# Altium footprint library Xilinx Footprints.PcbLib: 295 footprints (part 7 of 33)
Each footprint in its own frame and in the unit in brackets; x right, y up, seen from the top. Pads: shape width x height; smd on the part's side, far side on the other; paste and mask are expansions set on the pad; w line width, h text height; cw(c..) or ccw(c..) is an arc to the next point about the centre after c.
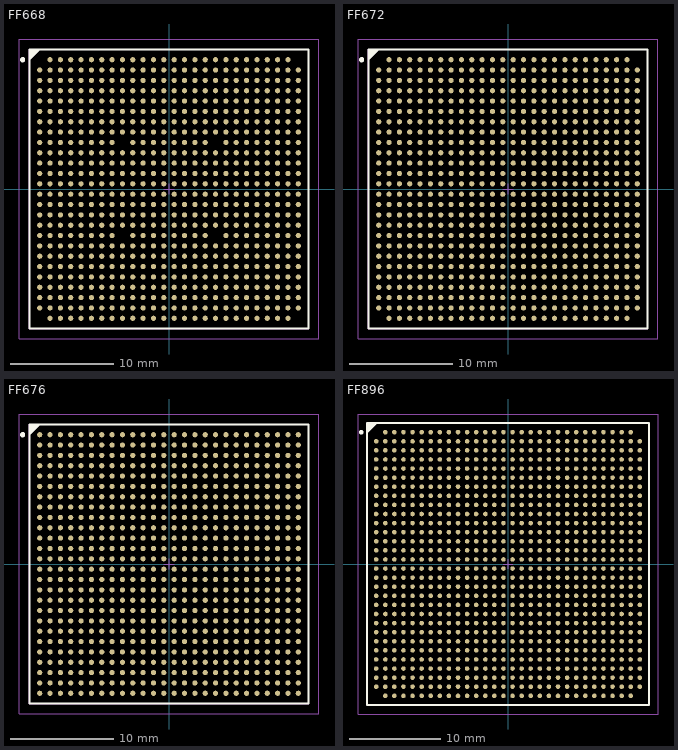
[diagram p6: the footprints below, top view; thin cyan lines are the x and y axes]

## FF668 [mm] "668-Ball Flip Chip Fine Pitch Ball Grid Array (FF668)"
height 2.85
pads (668):
  round 0.5 smd: A2(-11.5,12.5) A3(-10.5,12.5) A4(-9.5,12.5) A5(-8.5,12.5) A6(-7.5,12.5) A7(-6.5,12.5) A8(-5.5,12.5) A9(-4.5,12.5) A10(-3.5,12.5) A11(-2.5,12.5) A12(-1.5,12.5) A13(-0.5,12.5) A14(0.5,12.5) A15(1.5,12.5) A16(2.5,12.5) A17(3.5,12.5) A18(4.5,12.5) A19(5.5,12.5) A20(6.5,12.5) A21(7.5,12.5) A22(8.5,12.5) A23(9.5,12.5) A24(10.5,12.5) A25(11.5,12.5) AA1(-12.5,-7.5) AA2(-11.5,-7.5) AA3(-10.5,-7.5) AA4(-9.5,-7.5) AA5(-8.5,-7.5) AA6(-7.5,-7.5) AA7(-6.5,-7.5) AA8(-5.5,-7.5) AA9(-4.5,-7.5) AA10(-3.5,-7.5) AA11(-2.5,-7.5) AA12(-1.5,-7.5) AA13(-0.5,-7.5) AA14(0.5,-7.5) AA15(1.5,-7.5) AA16(2.5,-7.5) AA17(3.5,-7.5) AA18(4.5,-7.5) AA19(5.5,-7.5) AA20(6.5,-7.5) AA21(7.5,-7.5) AA22(8.5,-7.5) AA23(9.5,-7.5) AA24(10.5,-7.5) AA25(11.5,-7.5) AA26(12.5,-7.5) AB1(-12.5,-8.5) AB2(-11.5,-8.5) AB3(-10.5,-8.5) AB4(-9.5,-8.5) AB5(-8.5,-8.5) AB6(-7.5,-8.5) AB7(-6.5,-8.5) AB8(-5.5,-8.5) AB9(-4.5,-8.5) AB10(-3.5,-8.5) AB11(-2.5,-8.5) AB12(-1.5,-8.5) AB13(-0.5,-8.5) AB14(0.5,-8.5) AB15(1.5,-8.5) AB16(2.5,-8.5) AB17(3.5,-8.5) AB18(4.5,-8.5) AB19(5.5,-8.5) AB20(6.5,-8.5) AB21(7.5,-8.5) AB22(8.5,-8.5) AB23(9.5,-8.5) AB24(10.5,-8.5) AB25(11.5,-8.5) AB26(12.5,-8.5) AC1(-12.5,-9.5) AC2(-11.5,-9.5) AC3(-10.5,-9.5) AC4(-9.5,-9.5) AC5(-8.5,-9.5) AC6(-7.5,-9.5) AC7(-6.5,-9.5) AC8(-5.5,-9.5) AC9(-4.5,-9.5) AC10(-3.5,-9.5) AC11(-2.5,-9.5) AC12(-1.5,-9.5) AC13(-0.5,-9.5) AC14(0.5,-9.5) AC15(1.5,-9.5) AC16(2.5,-9.5) AC17(3.5,-9.5) AC18(4.5,-9.5) AC19(5.5,-9.5) AC20(6.5,-9.5) AC21(7.5,-9.5) AC22(8.5,-9.5) AC23(9.5,-9.5) AC24(10.5,-9.5) AC25(11.5,-9.5) AC26(12.5,-9.5) AD1(-12.5,-10.5) AD2(-11.5,-10.5) AD3(-10.5,-10.5) AD4(-9.5,-10.5) AD5(-8.5,-10.5) AD6(-7.5,-10.5) AD7(-6.5,-10.5) AD8(-5.5,-10.5) AD9(-4.5,-10.5) AD10(-3.5,-10.5) AD11(-2.5,-10.5) AD12(-1.5,-10.5) AD13(-0.5,-10.5) AD14(0.5,-10.5) AD15(1.5,-10.5) AD16(2.5,-10.5) AD17(3.5,-10.5) AD18(4.5,-10.5) AD19(5.5,-10.5) AD20(6.5,-10.5) AD21(7.5,-10.5) AD22(8.5,-10.5) AD23(9.5,-10.5) AD24(10.5,-10.5) AD25(11.5,-10.5) AD26(12.5,-10.5) AE1(-12.5,-11.5) AE2(-11.5,-11.5) AE3(-10.5,-11.5) AE4(-9.5,-11.5) AE5(-8.5,-11.5) AE6(-7.5,-11.5) AE7(-6.5,-11.5) AE8(-5.5,-11.5) AE9(-4.5,-11.5) AE10(-3.5,-11.5) AE11(-2.5,-11.5) AE12(-1.5,-11.5) AE13(-0.5,-11.5) AE14(0.5,-11.5) AE15(1.5,-11.5) AE16(2.5,-11.5) AE17(3.5,-11.5) AE18(4.5,-11.5) AE19(5.5,-11.5) AE20(6.5,-11.5) AE21(7.5,-11.5) AE22(8.5,-11.5) AE23(9.5,-11.5) AE24(10.5,-11.5) AE25(11.5,-11.5) AE26(12.5,-11.5) AF2(-11.5,-12.5) AF3(-10.5,-12.5) AF4(-9.5,-12.5) AF5(-8.5,-12.5) AF6(-7.5,-12.5) AF7(-6.5,-12.5) AF8(-5.5,-12.5) AF9(-4.5,-12.5) AF10(-3.5,-12.5) AF11(-2.5,-12.5) AF12(-1.5,-12.5) AF13(-0.5,-12.5) AF14(0.5,-12.5) AF15(1.5,-12.5) AF16(2.5,-12.5) AF17(3.5,-12.5) AF18(4.5,-12.5) AF19(5.5,-12.5) AF20(6.5,-12.5) AF21(7.5,-12.5) AF22(8.5,-12.5) AF23(9.5,-12.5) AF24(10.5,-12.5) AF25(11.5,-12.5) B1(-12.5,11.5) B2(-11.5,11.5) B3(-10.5,11.5) B4(-9.5,11.5) B5(-8.5,11.5) B6(-7.5,11.5) B7(-6.5,11.5) B8(-5.5,11.5) B9(-4.5,11.5) B10(-3.5,11.5) B11(-2.5,11.5) B12(-1.5,11.5) B13(-0.5,11.5) B14(0.5,11.5) B15(1.5,11.5) B16(2.5,11.5) B17(3.5,11.5) B18(4.5,11.5) B19(5.5,11.5) B20(6.5,11.5) B21(7.5,11.5) B22(8.5,11.5) B23(9.5,11.5) B24(10.5,11.5) B25(11.5,11.5) B26(12.5,11.5) C1(-12.5,10.5) C2(-11.5,10.5) C3(-10.5,10.5) C4(-9.5,10.5) C5(-8.5,10.5) C6(-7.5,10.5) C7(-6.5,10.5) C8(-5.5,10.5) C9(-4.5,10.5) C10(-3.5,10.5) C11(-2.5,10.5) C12(-1.5,10.5) C13(-0.5,10.5) C14(0.5,10.5) C15(1.5,10.5) C16(2.5,10.5) C17(3.5,10.5) C18(4.5,10.5) C19(5.5,10.5) C20(6.5,10.5) C21(7.5,10.5) C22(8.5,10.5) C23(9.5,10.5) C24(10.5,10.5) C25(11.5,10.5) C26(12.5,10.5) D1(-12.5,9.5) D2(-11.5,9.5) D3(-10.5,9.5) D4(-9.5,9.5) D5(-8.5,9.5) D6(-7.5,9.5) D7(-6.5,9.5) D8(-5.5,9.5) D9(-4.5,9.5) D10(-3.5,9.5) D11(-2.5,9.5) D12(-1.5,9.5) D13(-0.5,9.5) D14(0.5,9.5) D15(1.5,9.5) D16(2.5,9.5) D17(3.5,9.5) D18(4.5,9.5) D19(5.5,9.5) D20(6.5,9.5) D21(7.5,9.5) D22(8.5,9.5) D23(9.5,9.5) D24(10.5,9.5) D25(11.5,9.5) D26(12.5,9.5) E1(-12.5,8.5) E2(-11.5,8.5) E3(-10.5,8.5) E4(-9.5,8.5) E5(-8.5,8.5) E6(-7.5,8.5) E7(-6.5,8.5) E8(-5.5,8.5) E9(-4.5,8.5) E10(-3.5,8.5) E11(-2.5,8.5) E12(-1.5,8.5) E13(-0.5,8.5) E14(0.5,8.5) E15(1.5,8.5) E16(2.5,8.5) E17(3.5,8.5) E18(4.5,8.5) E19(5.5,8.5) E20(6.5,8.5) E21(7.5,8.5) E22(8.5,8.5) E23(9.5,8.5) E24(10.5,8.5) E25(11.5,8.5) E26(12.5,8.5) F1(-12.5,7.5) F2(-11.5,7.5) F3(-10.5,7.5) F4(-9.5,7.5) F5(-8.5,7.5) F6(-7.5,7.5) F7(-6.5,7.5) F8(-5.5,7.5) F9(-4.5,7.5) F10(-3.5,7.5) F11(-2.5,7.5) F12(-1.5,7.5) F13(-0.5,7.5) F14(0.5,7.5) F15(1.5,7.5) F16(2.5,7.5) F17(3.5,7.5) F18(4.5,7.5) F19(5.5,7.5) F20(6.5,7.5) F21(7.5,7.5) F22(8.5,7.5) F23(9.5,7.5) F24(10.5,7.5) F25(11.5,7.5) F26(12.5,7.5) G1(-12.5,6.5) G2(-11.5,6.5) G3(-10.5,6.5) G4(-9.5,6.5) G5(-8.5,6.5) G6(-7.5,6.5) G7(-6.5,6.5) G8(-5.5,6.5) G9(-4.5,6.5) G10(-3.5,6.5) G11(-2.5,6.5) G12(-1.5,6.5) G13(-0.5,6.5) G14(0.5,6.5) G15(1.5,6.5) G16(2.5,6.5) G17(3.5,6.5) G18(4.5,6.5) G19(5.5,6.5) G20(6.5,6.5) G21(7.5,6.5) G22(8.5,6.5) G23(9.5,6.5) G24(10.5,6.5) G25(11.5,6.5) G26(12.5,6.5) H1(-12.5,5.5) H2(-11.5,5.5) H3(-10.5,5.5) H4(-9.5,5.5) H5(-8.5,5.5) H6(-7.5,5.5) H7(-6.5,5.5) H8(-5.5,5.5) H9(-4.5,5.5) H10(-3.5,5.5) H11(-2.5,5.5) H12(-1.5,5.5) H13(-0.5,5.5) H14(0.5,5.5) H15(1.5,5.5) H16(2.5,5.5) H17(3.5,5.5) H18(4.5,5.5) H19(5.5,5.5) H20(6.5,5.5) H21(7.5,5.5) H22(8.5,5.5) H23(9.5,5.5) H24(10.5,5.5) H25(11.5,5.5) H26(12.5,5.5) J1(-12.5,4.5) J2(-11.5,4.5) J3(-10.5,4.5) J4(-9.5,4.5) J5(-8.5,4.5) J6(-7.5,4.5) J7(-6.5,4.5) J8(-5.5,4.5) J10(-3.5,4.5) J11(-2.5,4.5) J12(-1.5,4.5) J13(-0.5,4.5) J14(0.5,4.5) J15(1.5,4.5) J16(2.5,4.5) J17(3.5,4.5) J19(5.5,4.5) J20(6.5,4.5) J21(7.5,4.5) J22(8.5,4.5) J23(9.5,4.5) J24(10.5,4.5) J25(11.5,4.5) J26(12.5,4.5) K1(-12.5,3.5) K2(-11.5,3.5) K3(-10.5,3.5) K4(-9.5,3.5) K5(-8.5,3.5) K6(-7.5,3.5) K7(-6.5,3.5) K8(-5.5,3.5) K9(-4.5,3.5) K10(-3.5,3.5) K11(-2.5,3.5) K12(-1.5,3.5) K13(-0.5,3.5) K14(0.5,3.5) K15(1.5,3.5) K16(2.5,3.5) K17(3.5,3.5) K18(4.5,3.5) K19(5.5,3.5) K20(6.5,3.5) K21(7.5,3.5) K22(8.5,3.5) K23(9.5,3.5) K24(10.5,3.5) K25(11.5,3.5) K26(12.5,3.5) L1(-12.5,2.5) L2(-11.5,2.5) L3(-10.5,2.5) L4(-9.5,2.5) L5(-8.5,2.5) L6(-7.5,2.5) L7(-6.5,2.5) L8(-5.5,2.5) L9(-4.5,2.5) L10(-3.5,2.5) L11(-2.5,2.5) L12(-1.5,2.5) L13(-0.5,2.5) L14(0.5,2.5) L15(1.5,2.5) L16(2.5,2.5) L17(3.5,2.5) L18(4.5,2.5) L19(5.5,2.5) L20(6.5,2.5) L21(7.5,2.5) L22(8.5,2.5) L23(9.5,2.5) L24(10.5,2.5) L25(11.5,2.5) L26(12.5,2.5) M1(-12.5,1.5) M2(-11.5,1.5) M3(-10.5,1.5) M4(-9.5,1.5) M5(-8.5,1.5) M6(-7.5,1.5) M7(-6.5,1.5) M8(-5.5,1.5) M9(-4.5,1.5) M10(-3.5,1.5) M11(-2.5,1.5) M12(-1.5,1.5) M13(-0.5,1.5) M14(0.5,1.5) M15(1.5,1.5) M16(2.5,1.5) M17(3.5,1.5) M18(4.5,1.5) M19(5.5,1.5) M20(6.5,1.5) M21(7.5,1.5) M22(8.5,1.5) M23(9.5,1.5) M24(10.5,1.5) M25(11.5,1.5) M26(12.5,1.5) N1(-12.5,0.5) N2(-11.5,0.5) N3(-10.5,0.5) N4(-9.5,0.5) N5(-8.5,0.5) N6(-7.5,0.5) N7(-6.5,0.5) N8(-5.5,0.5) N9(-4.5,0.5) N10(-3.5,0.5) N11(-2.5,0.5) N12(-1.5,0.5) N13(-0.5,0.5) N14(0.5,0.5) N15(1.5,0.5) N16(2.5,0.5) N17(3.5,0.5) N18(4.5,0.5) N19(5.5,0.5) N20(6.5,0.5) N21(7.5,0.5) N22(8.5,0.5) N23(9.5,0.5) N24(10.5,0.5) N25(11.5,0.5) N26(12.5,0.5) P1(-12.5,-0.5) P2(-11.5,-0.5) P3(-10.5,-0.5) P4(-9.5,-0.5) P5(-8.5,-0.5) P6(-7.5,-0.5) P7(-6.5,-0.5) P8(-5.5,-0.5) P9(-4.5,-0.5) P10(-3.5,-0.5) P11(-2.5,-0.5) P12(-1.5,-0.5) P13(-0.5,-0.5) P14(0.5,-0.5) P15(1.5,-0.5) P16(2.5,-0.5) P17(3.5,-0.5) P18(4.5,-0.5) P19(5.5,-0.5) P20(6.5,-0.5) P21(7.5,-0.5) P22(8.5,-0.5) P23(9.5,-0.5) P24(10.5,-0.5) P25(11.5,-0.5) P26(12.5,-0.5) R1(-12.5,-1.5) R2(-11.5,-1.5) R3(-10.5,-1.5) R4(-9.5,-1.5) R5(-8.5,-1.5) R6(-7.5,-1.5) R7(-6.5,-1.5) R8(-5.5,-1.5) R9(-4.5,-1.5) R10(-3.5,-1.5) R11(-2.5,-1.5) R12(-1.5,-1.5) R13(-0.5,-1.5) R14(0.5,-1.5) R15(1.5,-1.5) R16(2.5,-1.5) R17(3.5,-1.5) R18(4.5,-1.5) R19(5.5,-1.5) R20(6.5,-1.5) R21(7.5,-1.5) R22(8.5,-1.5) R23(9.5,-1.5) R24(10.5,-1.5) R25(11.5,-1.5) R26(12.5,-1.5) T1(-12.5,-2.5) T2(-11.5,-2.5) T3(-10.5,-2.5) T4(-9.5,-2.5) T5(-8.5,-2.5) T6(-7.5,-2.5) T7(-6.5,-2.5) T8(-5.5,-2.5) T9(-4.5,-2.5) T10(-3.5,-2.5) T11(-2.5,-2.5) T12(-1.5,-2.5) T13(-0.5,-2.5) T14(0.5,-2.5) T15(1.5,-2.5) T16(2.5,-2.5) T17(3.5,-2.5) T18(4.5,-2.5) T19(5.5,-2.5) T20(6.5,-2.5) T21(7.5,-2.5) T22(8.5,-2.5) T23(9.5,-2.5) T24(10.5,-2.5) T25(11.5,-2.5) T26(12.5,-2.5) U1(-12.5,-3.5) U2(-11.5,-3.5) U3(-10.5,-3.5) U4(-9.5,-3.5) U5(-8.5,-3.5) U6(-7.5,-3.5) U7(-6.5,-3.5) U8(-5.5,-3.5) U9(-4.5,-3.5) U10(-3.5,-3.5) U11(-2.5,-3.5) U12(-1.5,-3.5) U13(-0.5,-3.5) U14(0.5,-3.5) U15(1.5,-3.5) U16(2.5,-3.5) U17(3.5,-3.5) U18(4.5,-3.5) U19(5.5,-3.5) U20(6.5,-3.5) U21(7.5,-3.5) U22(8.5,-3.5) U23(9.5,-3.5) U24(10.5,-3.5) U25(11.5,-3.5) U26(12.5,-3.5) V1(-12.5,-4.5) V2(-11.5,-4.5) V3(-10.5,-4.5) V4(-9.5,-4.5) V5(-8.5,-4.5) V6(-7.5,-4.5) V7(-6.5,-4.5) V8(-5.5,-4.5) V10(-3.5,-4.5) V11(-2.5,-4.5) V12(-1.5,-4.5) V13(-0.5,-4.5) V14(0.5,-4.5) V15(1.5,-4.5) V16(2.5,-4.5) V17(3.5,-4.5) V19(5.5,-4.5) V20(6.5,-4.5) V21(7.5,-4.5) V22(8.5,-4.5) V23(9.5,-4.5) V24(10.5,-4.5) V25(11.5,-4.5) V26(12.5,-4.5) W1(-12.5,-5.5) W2(-11.5,-5.5) W3(-10.5,-5.5) W4(-9.5,-5.5) W5(-8.5,-5.5) W6(-7.5,-5.5) W7(-6.5,-5.5) W8(-5.5,-5.5) W9(-4.5,-5.5) W10(-3.5,-5.5) W11(-2.5,-5.5) W12(-1.5,-5.5) W13(-0.5,-5.5) W14(0.5,-5.5) W15(1.5,-5.5) W16(2.5,-5.5) W17(3.5,-5.5) W18(4.5,-5.5) W19(5.5,-5.5) W20(6.5,-5.5) W21(7.5,-5.5) W22(8.5,-5.5) W23(9.5,-5.5) W24(10.5,-5.5) W25(11.5,-5.5) W26(12.5,-5.5) Y1(-12.5,-6.5) Y2(-11.5,-6.5) Y3(-10.5,-6.5) Y4(-9.5,-6.5) Y5(-8.5,-6.5) Y6(-7.5,-6.5) Y7(-6.5,-6.5) Y8(-5.5,-6.5) Y9(-4.5,-6.5) Y10(-3.5,-6.5) Y11(-2.5,-6.5) Y12(-1.5,-6.5) Y13(-0.5,-6.5) Y14(0.5,-6.5) Y15(1.5,-6.5) Y16(2.5,-6.5) Y17(3.5,-6.5) Y18(4.5,-6.5) Y19(5.5,-6.5) Y20(6.5,-6.5) Y21(7.5,-6.5) Y22(8.5,-6.5) Y23(9.5,-6.5) Y24(10.5,-6.5) Y25(11.5,-6.5) Y26(12.5,-6.5)
Top Overlay:
  circle w0.25: c-14.15,12.5 r0.125
  region: -12.5,13.5 -13.5,12.5 -13.5,13.5
  lines w0.2: -13.5,12.5 -12.5,13.5 ; -13.5,-13.5 -13.5,13.5 13.5,13.5 13.5,-13.5 -13.5,-13.5
Mechanical 13:
  lines w0.1: -13.5,-13.5 -13.5,13.5 13.5,13.5 13.5,-13.5 -13.5,-13.5
Mechanical 15:
  lines w0.1: -0.5,0 0.5,0 ; 0,-0.5 0,0.5 ; -14.5,-14.5 -14.5,14.5 14.5,14.5 14.5,-14.5 -14.5,-14.5
3D body: height 2.85, standoff 0, extent -13.5,-13.5 13.5,13.5

## FF672 [mm] "672-Ball Flip Chip Fine Pitch Ball Grid Array (FF672)"
height 3
pads (672):
  round 0.5 smd: A2(-11.5,12.5) A3(-10.5,12.5) A4(-9.5,12.5) A5(-8.5,12.5) A6(-7.5,12.5) A7(-6.5,12.5) A8(-5.5,12.5) A9(-4.5,12.5) A10(-3.5,12.5) A11(-2.5,12.5) A12(-1.5,12.5) A13(-0.5,12.5) A14(0.5,12.5) A15(1.5,12.5) A16(2.5,12.5) A17(3.5,12.5) A18(4.5,12.5) A19(5.5,12.5) A20(6.5,12.5) A21(7.5,12.5) A22(8.5,12.5) A23(9.5,12.5) A24(10.5,12.5) A25(11.5,12.5) AA1(-12.5,-7.5) AA2(-11.5,-7.5) AA3(-10.5,-7.5) AA4(-9.5,-7.5) AA5(-8.5,-7.5) AA6(-7.5,-7.5) AA7(-6.5,-7.5) AA8(-5.5,-7.5) AA9(-4.5,-7.5) AA10(-3.5,-7.5) AA11(-2.5,-7.5) AA12(-1.5,-7.5) AA13(-0.5,-7.5) AA14(0.5,-7.5) AA15(1.5,-7.5) AA16(2.5,-7.5) AA17(3.5,-7.5) AA18(4.5,-7.5) AA19(5.5,-7.5) AA20(6.5,-7.5) AA21(7.5,-7.5) AA22(8.5,-7.5) AA23(9.5,-7.5) AA24(10.5,-7.5) AA25(11.5,-7.5) AA26(12.5,-7.5) AB1(-12.5,-8.5) AB2(-11.5,-8.5) AB3(-10.5,-8.5) AB4(-9.5,-8.5) AB5(-8.5,-8.5) AB6(-7.5,-8.5) AB7(-6.5,-8.5) AB8(-5.5,-8.5) AB9(-4.5,-8.5) AB10(-3.5,-8.5) AB11(-2.5,-8.5) AB12(-1.5,-8.5) AB13(-0.5,-8.5) AB14(0.5,-8.5) AB15(1.5,-8.5) AB16(2.5,-8.5) AB17(3.5,-8.5) AB18(4.5,-8.5) AB19(5.5,-8.5) AB20(6.5,-8.5) AB21(7.5,-8.5) AB22(8.5,-8.5) AB23(9.5,-8.5) AB24(10.5,-8.5) AB25(11.5,-8.5) AB26(12.5,-8.5) AC1(-12.5,-9.5) AC2(-11.5,-9.5) AC3(-10.5,-9.5) AC4(-9.5,-9.5) AC5(-8.5,-9.5) AC6(-7.5,-9.5) AC7(-6.5,-9.5) AC8(-5.5,-9.5) AC9(-4.5,-9.5) AC10(-3.5,-9.5) AC11(-2.5,-9.5) AC12(-1.5,-9.5) AC13(-0.5,-9.5) AC14(0.5,-9.5) AC15(1.5,-9.5) AC16(2.5,-9.5) AC17(3.5,-9.5) AC18(4.5,-9.5) AC19(5.5,-9.5) AC20(6.5,-9.5) AC21(7.5,-9.5) AC22(8.5,-9.5) AC23(9.5,-9.5) AC24(10.5,-9.5) AC25(11.5,-9.5) AC26(12.5,-9.5) AD1(-12.5,-10.5) AD2(-11.5,-10.5) AD3(-10.5,-10.5) AD4(-9.5,-10.5) AD5(-8.5,-10.5) AD6(-7.5,-10.5) AD7(-6.5,-10.5) AD8(-5.5,-10.5) AD9(-4.5,-10.5) AD10(-3.5,-10.5) AD11(-2.5,-10.5) AD12(-1.5,-10.5) AD13(-0.5,-10.5) AD14(0.5,-10.5) AD15(1.5,-10.5) AD16(2.5,-10.5) AD17(3.5,-10.5) AD18(4.5,-10.5) AD19(5.5,-10.5) AD20(6.5,-10.5) AD21(7.5,-10.5) AD22(8.5,-10.5) AD23(9.5,-10.5) AD24(10.5,-10.5) AD25(11.5,-10.5) AD26(12.5,-10.5) AE1(-12.5,-11.5) AE2(-11.5,-11.5) AE3(-10.5,-11.5) AE4(-9.5,-11.5) AE5(-8.5,-11.5) AE6(-7.5,-11.5) AE7(-6.5,-11.5) AE8(-5.5,-11.5) AE9(-4.5,-11.5) AE10(-3.5,-11.5) AE11(-2.5,-11.5) AE12(-1.5,-11.5) AE13(-0.5,-11.5) AE14(0.5,-11.5) AE15(1.5,-11.5) AE16(2.5,-11.5) AE17(3.5,-11.5) AE18(4.5,-11.5) AE19(5.5,-11.5) AE20(6.5,-11.5) AE21(7.5,-11.5) AE22(8.5,-11.5) AE23(9.5,-11.5) AE24(10.5,-11.5) AE25(11.5,-11.5) AE26(12.5,-11.5) AF2(-11.5,-12.5) AF3(-10.5,-12.5) AF4(-9.5,-12.5) AF5(-8.5,-12.5) AF6(-7.5,-12.5) AF7(-6.5,-12.5) AF8(-5.5,-12.5) AF9(-4.5,-12.5) AF10(-3.5,-12.5) AF11(-2.5,-12.5) AF12(-1.5,-12.5) AF13(-0.5,-12.5) AF14(0.5,-12.5) AF15(1.5,-12.5) AF16(2.5,-12.5) AF17(3.5,-12.5) AF18(4.5,-12.5) AF19(5.5,-12.5) AF20(6.5,-12.5) AF21(7.5,-12.5) AF22(8.5,-12.5) AF23(9.5,-12.5) AF24(10.5,-12.5) AF25(11.5,-12.5) B1(-12.5,11.5) B2(-11.5,11.5) B3(-10.5,11.5) B4(-9.5,11.5) B5(-8.5,11.5) B6(-7.5,11.5) B7(-6.5,11.5) B8(-5.5,11.5) B9(-4.5,11.5) B10(-3.5,11.5) B11(-2.5,11.5) B12(-1.5,11.5) B13(-0.5,11.5) B14(0.5,11.5) B15(1.5,11.5) B16(2.5,11.5) B17(3.5,11.5) B18(4.5,11.5) B19(5.5,11.5) B20(6.5,11.5) B21(7.5,11.5) B22(8.5,11.5) B23(9.5,11.5) B24(10.5,11.5) B25(11.5,11.5) B26(12.5,11.5) C1(-12.5,10.5) C2(-11.5,10.5) C3(-10.5,10.5) C4(-9.5,10.5) C5(-8.5,10.5) C6(-7.5,10.5) C7(-6.5,10.5) C8(-5.5,10.5) C9(-4.5,10.5) C10(-3.5,10.5) C11(-2.5,10.5) C12(-1.5,10.5) C13(-0.5,10.5) C14(0.5,10.5) C15(1.5,10.5) C16(2.5,10.5) C17(3.5,10.5) C18(4.5,10.5) C19(5.5,10.5) C20(6.5,10.5) C21(7.5,10.5) C22(8.5,10.5) C23(9.5,10.5) C24(10.5,10.5) C25(11.5,10.5) C26(12.5,10.5) D1(-12.5,9.5) D2(-11.5,9.5) D3(-10.5,9.5) D4(-9.5,9.5) D5(-8.5,9.5) D6(-7.5,9.5) D7(-6.5,9.5) D8(-5.5,9.5) D9(-4.5,9.5) D10(-3.5,9.5) D11(-2.5,9.5) D12(-1.5,9.5) D13(-0.5,9.5) D14(0.5,9.5) D15(1.5,9.5) D16(2.5,9.5) D17(3.5,9.5) D18(4.5,9.5) D19(5.5,9.5) D20(6.5,9.5) D21(7.5,9.5) D22(8.5,9.5) D23(9.5,9.5) D24(10.5,9.5) D25(11.5,9.5) D26(12.5,9.5) E1(-12.5,8.5) E2(-11.5,8.5) E3(-10.5,8.5) E4(-9.5,8.5) E5(-8.5,8.5) E6(-7.5,8.5) E7(-6.5,8.5) E8(-5.5,8.5) E9(-4.5,8.5) E10(-3.5,8.5) E11(-2.5,8.5) E12(-1.5,8.5) E13(-0.5,8.5) E14(0.5,8.5) E15(1.5,8.5) E16(2.5,8.5) E17(3.5,8.5) E18(4.5,8.5) E19(5.5,8.5) E20(6.5,8.5) E21(7.5,8.5) E22(8.5,8.5) E23(9.5,8.5) E24(10.5,8.5) E25(11.5,8.5) E26(12.5,8.5) F1(-12.5,7.5) F2(-11.5,7.5) F3(-10.5,7.5) F4(-9.5,7.5) F5(-8.5,7.5) F6(-7.5,7.5) F7(-6.5,7.5) F8(-5.5,7.5) F9(-4.5,7.5) F10(-3.5,7.5) F11(-2.5,7.5) F12(-1.5,7.5) F13(-0.5,7.5) F14(0.5,7.5) F15(1.5,7.5) F16(2.5,7.5) F17(3.5,7.5) F18(4.5,7.5) F19(5.5,7.5) F20(6.5,7.5) F21(7.5,7.5) F22(8.5,7.5) F23(9.5,7.5) F24(10.5,7.5) F25(11.5,7.5) F26(12.5,7.5) G1(-12.5,6.5) G2(-11.5,6.5) G3(-10.5,6.5) G4(-9.5,6.5) G5(-8.5,6.5) G6(-7.5,6.5) G7(-6.5,6.5) G8(-5.5,6.5) G9(-4.5,6.5) G10(-3.5,6.5) G11(-2.5,6.5) G12(-1.5,6.5) G13(-0.5,6.5) G14(0.5,6.5) G15(1.5,6.5) G16(2.5,6.5) G17(3.5,6.5) G18(4.5,6.5) G19(5.5,6.5) G20(6.5,6.5) G21(7.5,6.5) G22(8.5,6.5) G23(9.5,6.5) G24(10.5,6.5) G25(11.5,6.5) G26(12.5,6.5) H1(-12.5,5.5) H2(-11.5,5.5) H3(-10.5,5.5) H4(-9.5,5.5) H5(-8.5,5.5) H6(-7.5,5.5) H7(-6.5,5.5) H8(-5.5,5.5) H9(-4.5,5.5) H10(-3.5,5.5) H11(-2.5,5.5) H12(-1.5,5.5) H13(-0.5,5.5) H14(0.5,5.5) H15(1.5,5.5) H16(2.5,5.5) H17(3.5,5.5) H18(4.5,5.5) H19(5.5,5.5) H20(6.5,5.5) H21(7.5,5.5) H22(8.5,5.5) H23(9.5,5.5) H24(10.5,5.5) H25(11.5,5.5) H26(12.5,5.5) J1(-12.5,4.5) J2(-11.5,4.5) J3(-10.5,4.5) J4(-9.5,4.5) J5(-8.5,4.5) J6(-7.5,4.5) J7(-6.5,4.5) J8(-5.5,4.5) J9(-4.5,4.5) J10(-3.5,4.5) J11(-2.5,4.5) J12(-1.5,4.5) J13(-0.5,4.5) J14(0.5,4.5) J15(1.5,4.5) J16(2.5,4.5) J17(3.5,4.5) J18(4.5,4.5) J19(5.5,4.5) J20(6.5,4.5) J21(7.5,4.5) J22(8.5,4.5) J23(9.5,4.5) J24(10.5,4.5) J25(11.5,4.5) J26(12.5,4.5) K1(-12.5,3.5) K2(-11.5,3.5) K3(-10.5,3.5) K4(-9.5,3.5) K5(-8.5,3.5) K6(-7.5,3.5) K7(-6.5,3.5) K8(-5.5,3.5) K9(-4.5,3.5) K10(-3.5,3.5) K11(-2.5,3.5) K12(-1.5,3.5) K13(-0.5,3.5) K14(0.5,3.5) K15(1.5,3.5) K16(2.5,3.5) K17(3.5,3.5) K18(4.5,3.5) K19(5.5,3.5) K20(6.5,3.5) K21(7.5,3.5) K22(8.5,3.5) K23(9.5,3.5) K24(10.5,3.5) K25(11.5,3.5) K26(12.5,3.5) L1(-12.5,2.5) L2(-11.5,2.5) L3(-10.5,2.5) L4(-9.5,2.5) L5(-8.5,2.5) L6(-7.5,2.5) L7(-6.5,2.5) L8(-5.5,2.5) L9(-4.5,2.5) L10(-3.5,2.5) L11(-2.5,2.5) L12(-1.5,2.5) L13(-0.5,2.5) L14(0.5,2.5) L15(1.5,2.5) L16(2.5,2.5) L17(3.5,2.5) L18(4.5,2.5) L19(5.5,2.5) L20(6.5,2.5) L21(7.5,2.5) L22(8.5,2.5) L23(9.5,2.5) L24(10.5,2.5) L25(11.5,2.5) L26(12.5,2.5) M1(-12.5,1.5) M2(-11.5,1.5) M3(-10.5,1.5) M4(-9.5,1.5) M5(-8.5,1.5) M6(-7.5,1.5) M7(-6.5,1.5) M8(-5.5,1.5) M9(-4.5,1.5) M10(-3.5,1.5) M11(-2.5,1.5) M12(-1.5,1.5) M13(-0.5,1.5) M14(0.5,1.5) M15(1.5,1.5) M16(2.5,1.5) M17(3.5,1.5) M18(4.5,1.5) M19(5.5,1.5) M20(6.5,1.5) M21(7.5,1.5) M22(8.5,1.5) M23(9.5,1.5) M24(10.5,1.5) M25(11.5,1.5) M26(12.5,1.5) N1(-12.5,0.5) N2(-11.5,0.5) N3(-10.5,0.5) N4(-9.5,0.5) N5(-8.5,0.5) N6(-7.5,0.5) N7(-6.5,0.5) N8(-5.5,0.5) N9(-4.5,0.5) N10(-3.5,0.5) N11(-2.5,0.5) N12(-1.5,0.5) N13(-0.5,0.5) N14(0.5,0.5) N15(1.5,0.5) N16(2.5,0.5) N17(3.5,0.5) N18(4.5,0.5) N19(5.5,0.5) N20(6.5,0.5) N21(7.5,0.5) N22(8.5,0.5) N23(9.5,0.5) N24(10.5,0.5) N25(11.5,0.5) N26(12.5,0.5) P1(-12.5,-0.5) P2(-11.5,-0.5) P3(-10.5,-0.5) P4(-9.5,-0.5) P5(-8.5,-0.5) P6(-7.5,-0.5) P7(-6.5,-0.5) P8(-5.5,-0.5) P9(-4.5,-0.5) P10(-3.5,-0.5) P11(-2.5,-0.5) P12(-1.5,-0.5) P13(-0.5,-0.5) P14(0.5,-0.5) P15(1.5,-0.5) P16(2.5,-0.5) P17(3.5,-0.5) P18(4.5,-0.5) P19(5.5,-0.5) P20(6.5,-0.5) P21(7.5,-0.5) P22(8.5,-0.5) P23(9.5,-0.5) P24(10.5,-0.5) P25(11.5,-0.5) P26(12.5,-0.5) R1(-12.5,-1.5) R2(-11.5,-1.5) R3(-10.5,-1.5) R4(-9.5,-1.5) R5(-8.5,-1.5) R6(-7.5,-1.5) R7(-6.5,-1.5) R8(-5.5,-1.5) R9(-4.5,-1.5) R10(-3.5,-1.5) R11(-2.5,-1.5) R12(-1.5,-1.5) R13(-0.5,-1.5) R14(0.5,-1.5) R15(1.5,-1.5) R16(2.5,-1.5) R17(3.5,-1.5) R18(4.5,-1.5) R19(5.5,-1.5) R20(6.5,-1.5) R21(7.5,-1.5) R22(8.5,-1.5) R23(9.5,-1.5) R24(10.5,-1.5) R25(11.5,-1.5) R26(12.5,-1.5) T1(-12.5,-2.5) T2(-11.5,-2.5) T3(-10.5,-2.5) T4(-9.5,-2.5) T5(-8.5,-2.5) T6(-7.5,-2.5) T7(-6.5,-2.5) T8(-5.5,-2.5) T9(-4.5,-2.5) T10(-3.5,-2.5) T11(-2.5,-2.5) T12(-1.5,-2.5) T13(-0.5,-2.5) T14(0.5,-2.5) T15(1.5,-2.5) T16(2.5,-2.5) T17(3.5,-2.5) T18(4.5,-2.5) T19(5.5,-2.5) T20(6.5,-2.5) T21(7.5,-2.5) T22(8.5,-2.5) T23(9.5,-2.5) T24(10.5,-2.5) T25(11.5,-2.5) T26(12.5,-2.5) U1(-12.5,-3.5) U2(-11.5,-3.5) U3(-10.5,-3.5) U4(-9.5,-3.5) U5(-8.5,-3.5) U6(-7.5,-3.5) U7(-6.5,-3.5) U8(-5.5,-3.5) U9(-4.5,-3.5) U10(-3.5,-3.5) U11(-2.5,-3.5) U12(-1.5,-3.5) U13(-0.5,-3.5) U14(0.5,-3.5) U15(1.5,-3.5) U16(2.5,-3.5) U17(3.5,-3.5) U18(4.5,-3.5) U19(5.5,-3.5) U20(6.5,-3.5) U21(7.5,-3.5) U22(8.5,-3.5) U23(9.5,-3.5) U24(10.5,-3.5) U25(11.5,-3.5) U26(12.5,-3.5) V1(-12.5,-4.5) V2(-11.5,-4.5) V3(-10.5,-4.5) V4(-9.5,-4.5) V5(-8.5,-4.5) V6(-7.5,-4.5) V7(-6.5,-4.5) V8(-5.5,-4.5) V9(-4.5,-4.5) V10(-3.5,-4.5) V11(-2.5,-4.5) V12(-1.5,-4.5) V13(-0.5,-4.5) V14(0.5,-4.5) V15(1.5,-4.5) V16(2.5,-4.5) V17(3.5,-4.5) V18(4.5,-4.5) V19(5.5,-4.5) V20(6.5,-4.5) V21(7.5,-4.5) V22(8.5,-4.5) V23(9.5,-4.5) V24(10.5,-4.5) V25(11.5,-4.5) V26(12.5,-4.5) W1(-12.5,-5.5) W2(-11.5,-5.5) W3(-10.5,-5.5) W4(-9.5,-5.5) W5(-8.5,-5.5) W6(-7.5,-5.5) W7(-6.5,-5.5) W8(-5.5,-5.5) W9(-4.5,-5.5) W10(-3.5,-5.5) W11(-2.5,-5.5) W12(-1.5,-5.5) W13(-0.5,-5.5) W14(0.5,-5.5) W15(1.5,-5.5) W16(2.5,-5.5) W17(3.5,-5.5) W18(4.5,-5.5) W19(5.5,-5.5) W20(6.5,-5.5) W21(7.5,-5.5) W22(8.5,-5.5) W23(9.5,-5.5) W24(10.5,-5.5) W25(11.5,-5.5) W26(12.5,-5.5) Y1(-12.5,-6.5) Y2(-11.5,-6.5) Y3(-10.5,-6.5) Y4(-9.5,-6.5) Y5(-8.5,-6.5) Y6(-7.5,-6.5) Y7(-6.5,-6.5) Y8(-5.5,-6.5) Y9(-4.5,-6.5) Y10(-3.5,-6.5) Y11(-2.5,-6.5) Y12(-1.5,-6.5) Y13(-0.5,-6.5) Y14(0.5,-6.5) Y15(1.5,-6.5) Y16(2.5,-6.5) Y17(3.5,-6.5) Y18(4.5,-6.5) Y19(5.5,-6.5) Y20(6.5,-6.5) Y21(7.5,-6.5) Y22(8.5,-6.5) Y23(9.5,-6.5) Y24(10.5,-6.5) Y25(11.5,-6.5) Y26(12.5,-6.5)
Top Overlay:
  circle w0.25: c-14.15,12.5 r0.125
  region: -12.5,13.5 -13.5,12.5 -13.5,13.5
  lines w0.2: -13.5,12.5 -12.5,13.5 ; -13.5,-13.5 13.5,-13.5 13.5,13.5 -13.5,13.5 -13.5,-13.5
Mechanical 13:
  lines w0.1: -13.5,-13.5 13.5,-13.5 13.5,13.5 -13.5,13.5 -13.5,-13.5
Mechanical 15:
  lines w0.1: -0.5,0 0.5,0 ; 0,-0.5 0,0.5 ; -14.5,-14.5 14.5,-14.5 14.5,14.5 -14.5,14.5 -14.5,-14.5
3D body: height 3, standoff 0, extent -13.5,-13.5 13.5,13.5

## FF676 [mm] "676-Ball Flip Chip Fine Pitch Ball Grid Array (FF676)"
height 3
pads (676):
  round 0.5 smd: A1(-12.5,12.5) A2(-11.5,12.5) A3(-10.5,12.5) A4(-9.5,12.5) A5(-8.5,12.5) A6(-7.5,12.5) A7(-6.5,12.5) A8(-5.5,12.5) A9(-4.5,12.5) A10(-3.5,12.5) A11(-2.5,12.5) A12(-1.5,12.5) A13(-0.5,12.5) A14(0.5,12.5) A15(1.5,12.5) A16(2.5,12.5) A17(3.5,12.5) A18(4.5,12.5) A19(5.5,12.5) A20(6.5,12.5) A21(7.5,12.5) A22(8.5,12.5) A23(9.5,12.5) A24(10.5,12.5) A25(11.5,12.5) A26(12.5,12.5) AA1(-12.5,-7.5) AA2(-11.5,-7.5) AA3(-10.5,-7.5) AA4(-9.5,-7.5) AA5(-8.5,-7.5) AA6(-7.5,-7.5) AA7(-6.5,-7.5) AA8(-5.5,-7.5) AA9(-4.5,-7.5) AA10(-3.5,-7.5) AA11(-2.5,-7.5) AA12(-1.5,-7.5) AA13(-0.5,-7.5) AA14(0.5,-7.5) AA15(1.5,-7.5) AA16(2.5,-7.5) AA17(3.5,-7.5) AA18(4.5,-7.5) AA19(5.5,-7.5) AA20(6.5,-7.5) AA21(7.5,-7.5) AA22(8.5,-7.5) AA23(9.5,-7.5) AA24(10.5,-7.5) AA25(11.5,-7.5) AA26(12.5,-7.5) AB1(-12.5,-8.5) AB2(-11.5,-8.5) AB3(-10.5,-8.5) AB4(-9.5,-8.5) AB5(-8.5,-8.5) AB6(-7.5,-8.5) AB7(-6.5,-8.5) AB8(-5.5,-8.5) AB9(-4.5,-8.5) AB10(-3.5,-8.5) AB11(-2.5,-8.5) AB12(-1.5,-8.5) AB13(-0.5,-8.5) AB14(0.5,-8.5) AB15(1.5,-8.5) AB16(2.5,-8.5) AB17(3.5,-8.5) AB18(4.5,-8.5) AB19(5.5,-8.5) AB20(6.5,-8.5) AB21(7.5,-8.5) AB22(8.5,-8.5) AB23(9.5,-8.5) AB24(10.5,-8.5) AB25(11.5,-8.5) AB26(12.5,-8.5) AC1(-12.5,-9.5) AC2(-11.5,-9.5) AC3(-10.5,-9.5) AC4(-9.5,-9.5) AC5(-8.5,-9.5) AC6(-7.5,-9.5) AC7(-6.5,-9.5) AC8(-5.5,-9.5) AC9(-4.5,-9.5) AC10(-3.5,-9.5) AC11(-2.5,-9.5) AC12(-1.5,-9.5) AC13(-0.5,-9.5) AC14(0.5,-9.5) AC15(1.5,-9.5) AC16(2.5,-9.5) AC17(3.5,-9.5) AC18(4.5,-9.5) AC19(5.5,-9.5) AC20(6.5,-9.5) AC21(7.5,-9.5) AC22(8.5,-9.5) AC23(9.5,-9.5) AC24(10.5,-9.5) AC25(11.5,-9.5) AC26(12.5,-9.5) AD1(-12.5,-10.5) AD2(-11.5,-10.5) AD3(-10.5,-10.5) AD4(-9.5,-10.5) AD5(-8.5,-10.5) AD6(-7.5,-10.5) AD7(-6.5,-10.5) AD8(-5.5,-10.5) AD9(-4.5,-10.5) AD10(-3.5,-10.5) AD11(-2.5,-10.5) AD12(-1.5,-10.5) AD13(-0.5,-10.5) AD14(0.5,-10.5) AD15(1.5,-10.5) AD16(2.5,-10.5) AD17(3.5,-10.5) AD18(4.5,-10.5) AD19(5.5,-10.5) AD20(6.5,-10.5) AD21(7.5,-10.5) AD22(8.5,-10.5) AD23(9.5,-10.5) AD24(10.5,-10.5) AD25(11.5,-10.5) AD26(12.5,-10.5) AE1(-12.5,-11.5) AE2(-11.5,-11.5) AE3(-10.5,-11.5) AE4(-9.5,-11.5) AE5(-8.5,-11.5) AE6(-7.5,-11.5) AE7(-6.5,-11.5) AE8(-5.5,-11.5) AE9(-4.5,-11.5) AE10(-3.5,-11.5) AE11(-2.5,-11.5) AE12(-1.5,-11.5) AE13(-0.5,-11.5) AE14(0.5,-11.5) AE15(1.5,-11.5) AE16(2.5,-11.5) AE17(3.5,-11.5) AE18(4.5,-11.5) AE19(5.5,-11.5) AE20(6.5,-11.5) AE21(7.5,-11.5) AE22(8.5,-11.5) AE23(9.5,-11.5) AE24(10.5,-11.5) AE25(11.5,-11.5) AE26(12.5,-11.5) AF1(-12.5,-12.5) AF2(-11.5,-12.5) AF3(-10.5,-12.5) AF4(-9.5,-12.5) AF5(-8.5,-12.5) AF6(-7.5,-12.5) AF7(-6.5,-12.5) AF8(-5.5,-12.5) AF9(-4.5,-12.5) AF10(-3.5,-12.5) AF11(-2.5,-12.5) AF12(-1.5,-12.5) AF13(-0.5,-12.5) AF14(0.5,-12.5) AF15(1.5,-12.5) AF16(2.5,-12.5) AF17(3.5,-12.5) AF18(4.5,-12.5) AF19(5.5,-12.5) AF20(6.5,-12.5) AF21(7.5,-12.5) AF22(8.5,-12.5) AF23(9.5,-12.5) AF24(10.5,-12.5) AF25(11.5,-12.5) AF26(12.5,-12.5) B1(-12.5,11.5) B2(-11.5,11.5) B3(-10.5,11.5) B4(-9.5,11.5) B5(-8.5,11.5) B6(-7.5,11.5) B7(-6.5,11.5) B8(-5.5,11.5) B9(-4.5,11.5) B10(-3.5,11.5) B11(-2.5,11.5) B12(-1.5,11.5) B13(-0.5,11.5) B14(0.5,11.5) B15(1.5,11.5) B16(2.5,11.5) B17(3.5,11.5) B18(4.5,11.5) B19(5.5,11.5) B20(6.5,11.5) B21(7.5,11.5) B22(8.5,11.5) B23(9.5,11.5) B24(10.5,11.5) B25(11.5,11.5) B26(12.5,11.5) C1(-12.5,10.5) C2(-11.5,10.5) C3(-10.5,10.5) C4(-9.5,10.5) C5(-8.5,10.5) C6(-7.5,10.5) C7(-6.5,10.5) C8(-5.5,10.5) C9(-4.5,10.5) C10(-3.5,10.5) C11(-2.5,10.5) C12(-1.5,10.5) C13(-0.5,10.5) C14(0.5,10.5) C15(1.5,10.5) C16(2.5,10.5) C17(3.5,10.5) C18(4.5,10.5) C19(5.5,10.5) C20(6.5,10.5) C21(7.5,10.5) C22(8.5,10.5) C23(9.5,10.5) C24(10.5,10.5) C25(11.5,10.5) C26(12.5,10.5) D1(-12.5,9.5) D2(-11.5,9.5) D3(-10.5,9.5) D4(-9.5,9.5) D5(-8.5,9.5) D6(-7.5,9.5) D7(-6.5,9.5) D8(-5.5,9.5) D9(-4.5,9.5) D10(-3.5,9.5) D11(-2.5,9.5) D12(-1.5,9.5) D13(-0.5,9.5) D14(0.5,9.5) D15(1.5,9.5) D16(2.5,9.5) D17(3.5,9.5) D18(4.5,9.5) D19(5.5,9.5) D20(6.5,9.5) D21(7.5,9.5) D22(8.5,9.5) D23(9.5,9.5) D24(10.5,9.5) D25(11.5,9.5) D26(12.5,9.5) E1(-12.5,8.5) E2(-11.5,8.5) E3(-10.5,8.5) E4(-9.5,8.5) E5(-8.5,8.5) E6(-7.5,8.5) E7(-6.5,8.5) E8(-5.5,8.5) E9(-4.5,8.5) E10(-3.5,8.5) E11(-2.5,8.5) E12(-1.5,8.5) E13(-0.5,8.5) E14(0.5,8.5) E15(1.5,8.5) E16(2.5,8.5) E17(3.5,8.5) E18(4.5,8.5) E19(5.5,8.5) E20(6.5,8.5) E21(7.5,8.5) E22(8.5,8.5) E23(9.5,8.5) E24(10.5,8.5) E25(11.5,8.5) E26(12.5,8.5) F1(-12.5,7.5) F2(-11.5,7.5) F3(-10.5,7.5) F4(-9.5,7.5) F5(-8.5,7.5) F6(-7.5,7.5) F7(-6.5,7.5) F8(-5.5,7.5) F9(-4.5,7.5) F10(-3.5,7.5) F11(-2.5,7.5) F12(-1.5,7.5) F13(-0.5,7.5) F14(0.5,7.5) F15(1.5,7.5) F16(2.5,7.5) F17(3.5,7.5) F18(4.5,7.5) F19(5.5,7.5) F20(6.5,7.5) F21(7.5,7.5) F22(8.5,7.5) F23(9.5,7.5) F24(10.5,7.5) F25(11.5,7.5) F26(12.5,7.5) G1(-12.5,6.5) G2(-11.5,6.5) G3(-10.5,6.5) G4(-9.5,6.5) G5(-8.5,6.5) G6(-7.5,6.5) G7(-6.5,6.5) G8(-5.5,6.5) G9(-4.5,6.5) G10(-3.5,6.5) G11(-2.5,6.5) G12(-1.5,6.5) G13(-0.5,6.5) G14(0.5,6.5) G15(1.5,6.5) G16(2.5,6.5) G17(3.5,6.5) G18(4.5,6.5) G19(5.5,6.5) G20(6.5,6.5) G21(7.5,6.5) G22(8.5,6.5) G23(9.5,6.5) G24(10.5,6.5) G25(11.5,6.5) G26(12.5,6.5) H1(-12.5,5.5) H2(-11.5,5.5) H3(-10.5,5.5) H4(-9.5,5.5) H5(-8.5,5.5) H6(-7.5,5.5) H7(-6.5,5.5) H8(-5.5,5.5) H9(-4.5,5.5) H10(-3.5,5.5) H11(-2.5,5.5) H12(-1.5,5.5) H13(-0.5,5.5) H14(0.5,5.5) H15(1.5,5.5) H16(2.5,5.5) H17(3.5,5.5) H18(4.5,5.5) H19(5.5,5.5) H20(6.5,5.5) H21(7.5,5.5) H22(8.5,5.5) H23(9.5,5.5) H24(10.5,5.5) H25(11.5,5.5) H26(12.5,5.5) J1(-12.5,4.5) J2(-11.5,4.5) J3(-10.5,4.5) J4(-9.5,4.5) J5(-8.5,4.5) J6(-7.5,4.5) J7(-6.5,4.5) J8(-5.5,4.5) J9(-4.5,4.5) J10(-3.5,4.5) J11(-2.5,4.5) J12(-1.5,4.5) J13(-0.5,4.5) J14(0.5,4.5) J15(1.5,4.5) J16(2.5,4.5) J17(3.5,4.5) J18(4.5,4.5) J19(5.5,4.5) J20(6.5,4.5) J21(7.5,4.5) J22(8.5,4.5) J23(9.5,4.5) J24(10.5,4.5) J25(11.5,4.5) J26(12.5,4.5) K1(-12.5,3.5) K2(-11.5,3.5) K3(-10.5,3.5) K4(-9.5,3.5) K5(-8.5,3.5) K6(-7.5,3.5) K7(-6.5,3.5) K8(-5.5,3.5) K9(-4.5,3.5) K10(-3.5,3.5) K11(-2.5,3.5) K12(-1.5,3.5) K13(-0.5,3.5) K14(0.5,3.5) K15(1.5,3.5) K16(2.5,3.5) K17(3.5,3.5) K18(4.5,3.5) K19(5.5,3.5) K20(6.5,3.5) K21(7.5,3.5) K22(8.5,3.5) K23(9.5,3.5) K24(10.5,3.5) K25(11.5,3.5) K26(12.5,3.5) L1(-12.5,2.5) L2(-11.5,2.5) L3(-10.5,2.5) L4(-9.5,2.5) L5(-8.5,2.5) L6(-7.5,2.5) L7(-6.5,2.5) L8(-5.5,2.5) L9(-4.5,2.5) L10(-3.5,2.5) L11(-2.5,2.5) L12(-1.5,2.5) L13(-0.5,2.5) L14(0.5,2.5) L15(1.5,2.5) L16(2.5,2.5) L17(3.5,2.5) L18(4.5,2.5) L19(5.5,2.5) L20(6.5,2.5) L21(7.5,2.5) L22(8.5,2.5) L23(9.5,2.5) L24(10.5,2.5) L25(11.5,2.5) L26(12.5,2.5) M1(-12.5,1.5) M2(-11.5,1.5) M3(-10.5,1.5) M4(-9.5,1.5) M5(-8.5,1.5) M6(-7.5,1.5) M7(-6.5,1.5) M8(-5.5,1.5) M9(-4.5,1.5) M10(-3.5,1.5) M11(-2.5,1.5) M12(-1.5,1.5) M13(-0.5,1.5) M14(0.5,1.5) M15(1.5,1.5) M16(2.5,1.5) M17(3.5,1.5) M18(4.5,1.5) M19(5.5,1.5) M20(6.5,1.5) M21(7.5,1.5) M22(8.5,1.5) M23(9.5,1.5) M24(10.5,1.5) M25(11.5,1.5) M26(12.5,1.5) N1(-12.5,0.5) N2(-11.5,0.5) N3(-10.5,0.5) N4(-9.5,0.5) N5(-8.5,0.5) N6(-7.5,0.5) N7(-6.5,0.5) N8(-5.5,0.5) N9(-4.5,0.5) N10(-3.5,0.5) N11(-2.5,0.5) N12(-1.5,0.5) N13(-0.5,0.5) N14(0.5,0.5) N15(1.5,0.5) N16(2.5,0.5) N17(3.5,0.5) N18(4.5,0.5) N19(5.5,0.5) N20(6.5,0.5) N21(7.5,0.5) N22(8.5,0.5) N23(9.5,0.5) N24(10.5,0.5) N25(11.5,0.5) N26(12.5,0.5) P1(-12.5,-0.5) P2(-11.5,-0.5) P3(-10.5,-0.5) P4(-9.5,-0.5) P5(-8.5,-0.5) P6(-7.5,-0.5) P7(-6.5,-0.5) P8(-5.5,-0.5) P9(-4.5,-0.5) P10(-3.5,-0.5) P11(-2.5,-0.5) P12(-1.5,-0.5) P13(-0.5,-0.5) P14(0.5,-0.5) P15(1.5,-0.5) P16(2.5,-0.5) P17(3.5,-0.5) P18(4.5,-0.5) P19(5.5,-0.5) P20(6.5,-0.5) P21(7.5,-0.5) P22(8.5,-0.5) P23(9.5,-0.5) P24(10.5,-0.5) P25(11.5,-0.5) P26(12.5,-0.5) R1(-12.5,-1.5) R2(-11.5,-1.5) R3(-10.5,-1.5) R4(-9.5,-1.5) R5(-8.5,-1.5) R6(-7.5,-1.5) R7(-6.5,-1.5) R8(-5.5,-1.5) R9(-4.5,-1.5) R10(-3.5,-1.5) R11(-2.5,-1.5) R12(-1.5,-1.5) R13(-0.5,-1.5) R14(0.5,-1.5) R15(1.5,-1.5) R16(2.5,-1.5) R17(3.5,-1.5) R18(4.5,-1.5) R19(5.5,-1.5) R20(6.5,-1.5) R21(7.5,-1.5) R22(8.5,-1.5) R23(9.5,-1.5) R24(10.5,-1.5) R25(11.5,-1.5) R26(12.5,-1.5) T1(-12.5,-2.5) T2(-11.5,-2.5) T3(-10.5,-2.5) T4(-9.5,-2.5) T5(-8.5,-2.5) T6(-7.5,-2.5) T7(-6.5,-2.5) T8(-5.5,-2.5) T9(-4.5,-2.5) T10(-3.5,-2.5) T11(-2.5,-2.5) T12(-1.5,-2.5) T13(-0.5,-2.5) T14(0.5,-2.5) T15(1.5,-2.5) T16(2.5,-2.5) T17(3.5,-2.5) T18(4.5,-2.5) T19(5.5,-2.5) T20(6.5,-2.5) T21(7.5,-2.5) T22(8.5,-2.5) T23(9.5,-2.5) T24(10.5,-2.5) T25(11.5,-2.5) T26(12.5,-2.5) U1(-12.5,-3.5) U2(-11.5,-3.5) U3(-10.5,-3.5) U4(-9.5,-3.5) U5(-8.5,-3.5) U6(-7.5,-3.5) U7(-6.5,-3.5) U8(-5.5,-3.5) U9(-4.5,-3.5) U10(-3.5,-3.5) U11(-2.5,-3.5) U12(-1.5,-3.5) U13(-0.5,-3.5) U14(0.5,-3.5) U15(1.5,-3.5) U16(2.5,-3.5) U17(3.5,-3.5) U18(4.5,-3.5) U19(5.5,-3.5) U20(6.5,-3.5) U21(7.5,-3.5) U22(8.5,-3.5) U23(9.5,-3.5) U24(10.5,-3.5) U25(11.5,-3.5) U26(12.5,-3.5) V1(-12.5,-4.5) V2(-11.5,-4.5) V3(-10.5,-4.5) V4(-9.5,-4.5) V5(-8.5,-4.5) V6(-7.5,-4.5) V7(-6.5,-4.5) V8(-5.5,-4.5) V9(-4.5,-4.5) V10(-3.5,-4.5) V11(-2.5,-4.5) V12(-1.5,-4.5) V13(-0.5,-4.5) V14(0.5,-4.5) V15(1.5,-4.5) V16(2.5,-4.5) V17(3.5,-4.5) V18(4.5,-4.5) V19(5.5,-4.5) V20(6.5,-4.5) V21(7.5,-4.5) V22(8.5,-4.5) V23(9.5,-4.5) V24(10.5,-4.5) V25(11.5,-4.5) V26(12.5,-4.5) W1(-12.5,-5.5) W2(-11.5,-5.5) W3(-10.5,-5.5) W4(-9.5,-5.5) W5(-8.5,-5.5) W6(-7.5,-5.5) W7(-6.5,-5.5) W8(-5.5,-5.5) W9(-4.5,-5.5) W10(-3.5,-5.5) W11(-2.5,-5.5) W12(-1.5,-5.5) W13(-0.5,-5.5) W14(0.5,-5.5) W15(1.5,-5.5) W16(2.5,-5.5) W17(3.5,-5.5) W18(4.5,-5.5) W19(5.5,-5.5) W20(6.5,-5.5) W21(7.5,-5.5) W22(8.5,-5.5) W23(9.5,-5.5) W24(10.5,-5.5) W25(11.5,-5.5) W26(12.5,-5.5) Y1(-12.5,-6.5) Y2(-11.5,-6.5) Y3(-10.5,-6.5) Y4(-9.5,-6.5) Y5(-8.5,-6.5) Y6(-7.5,-6.5) Y7(-6.5,-6.5) Y8(-5.5,-6.5) Y9(-4.5,-6.5) Y10(-3.5,-6.5) Y11(-2.5,-6.5) Y12(-1.5,-6.5) Y13(-0.5,-6.5) Y14(0.5,-6.5) Y15(1.5,-6.5) Y16(2.5,-6.5) Y17(3.5,-6.5) Y18(4.5,-6.5) Y19(5.5,-6.5) Y20(6.5,-6.5) Y21(7.5,-6.5) Y22(8.5,-6.5) Y23(9.5,-6.5) Y24(10.5,-6.5) Y25(11.5,-6.5) Y26(12.5,-6.5)
Top Overlay:
  circle w0.25: c-14.15,12.5 r0.125
  region: -12.5,13.5 -13.5,12.5 -13.5,13.5
  lines w0.2: -13.5,12.5 -12.5,13.5 ; -13.5,-13.5 13.5,-13.5 13.5,13.5 -13.5,13.5 -13.5,-13.5
Mechanical 13:
  lines w0.1: -13.5,-13.5 13.5,-13.5 13.5,13.5 -13.5,13.5 -13.5,-13.5
Mechanical 15:
  lines w0.1: -0.5,0 0.5,0 ; 0,-0.5 0,0.5 ; -14.5,-14.5 14.5,-14.5 14.5,14.5 -14.5,14.5 -14.5,-14.5
3D body: height 3, standoff 0, extent -13.5,-13.5 13.5,13.5

## FF896 [mm] "896-Ball Flip Chip Fine Pitch Ball Grid Array (FF896)"
height 3.4
pads (896):
  round 0.5 smd: A2(-13.5,14.5) A3(-12.5,14.5) A4(-11.5,14.5) A5(-10.5,14.5) A6(-9.5,14.5) A7(-8.5,14.5) A8(-7.5,14.5) A9(-6.5,14.5) A10(-5.5,14.5) A11(-4.5,14.5) A12(-3.5,14.5) A13(-2.5,14.5) A14(-1.5,14.5) A15(-0.5,14.5) A16(0.5,14.5) A17(1.5,14.5) A18(2.5,14.5) A19(3.5,14.5) A20(4.5,14.5) A21(5.5,14.5) A22(6.5,14.5) A23(7.5,14.5) A24(8.5,14.5) A25(9.5,14.5) A26(10.5,14.5) A27(11.5,14.5) A28(12.5,14.5) A29(13.5,14.5) AA1(-14.5,-5.5) AA2(-13.5,-5.5) AA3(-12.5,-5.5) AA4(-11.5,-5.5) AA5(-10.5,-5.5) AA6(-9.5,-5.5) AA7(-8.5,-5.5) AA8(-7.5,-5.5) AA9(-6.5,-5.5) AA10(-5.5,-5.5) AA11(-4.5,-5.5) AA12(-3.5,-5.5) AA13(-2.5,-5.5) AA14(-1.5,-5.5) AA15(-0.5,-5.5) AA16(0.5,-5.5) AA17(1.5,-5.5) AA18(2.5,-5.5) AA19(3.5,-5.5) AA20(4.5,-5.5) AA21(5.5,-5.5) AA22(6.5,-5.5) AA23(7.5,-5.5) AA24(8.5,-5.5) AA25(9.5,-5.5) AA26(10.5,-5.5) AA27(11.5,-5.5) AA28(12.5,-5.5) AA29(13.5,-5.5) AA30(14.5,-5.5) AB1(-14.5,-6.5) AB2(-13.5,-6.5) AB3(-12.5,-6.5) AB4(-11.5,-6.5) AB5(-10.5,-6.5) AB6(-9.5,-6.5) AB7(-8.5,-6.5) AB8(-7.5,-6.5) AB9(-6.5,-6.5) AB10(-5.5,-6.5) AB11(-4.5,-6.5) AB12(-3.5,-6.5) AB13(-2.5,-6.5) AB14(-1.5,-6.5) AB15(-0.5,-6.5) AB16(0.5,-6.5) AB17(1.5,-6.5) AB18(2.5,-6.5) AB19(3.5,-6.5) AB20(4.5,-6.5) AB21(5.5,-6.5) AB22(6.5,-6.5) AB23(7.5,-6.5) AB24(8.5,-6.5) AB25(9.5,-6.5) AB26(10.5,-6.5) AB27(11.5,-6.5) AB28(12.5,-6.5) AB29(13.5,-6.5) AB30(14.5,-6.5) AC1(-14.5,-7.5) AC2(-13.5,-7.5) AC3(-12.5,-7.5) AC4(-11.5,-7.5) AC5(-10.5,-7.5) AC6(-9.5,-7.5) AC7(-8.5,-7.5) AC8(-7.5,-7.5) AC9(-6.5,-7.5) AC10(-5.5,-7.5) AC11(-4.5,-7.5) AC12(-3.5,-7.5) AC13(-2.5,-7.5) AC14(-1.5,-7.5) AC15(-0.5,-7.5) AC16(0.5,-7.5) AC17(1.5,-7.5) AC18(2.5,-7.5) AC19(3.5,-7.5) AC20(4.5,-7.5) AC21(5.5,-7.5) AC22(6.5,-7.5) AC23(7.5,-7.5) AC24(8.5,-7.5) AC25(9.5,-7.5) AC26(10.5,-7.5) AC27(11.5,-7.5) AC28(12.5,-7.5) AC29(13.5,-7.5) AC30(14.5,-7.5) AD1(-14.5,-8.5) AD2(-13.5,-8.5) AD3(-12.5,-8.5) AD4(-11.5,-8.5) AD5(-10.5,-8.5) AD6(-9.5,-8.5) AD7(-8.5,-8.5) AD8(-7.5,-8.5) AD9(-6.5,-8.5) AD10(-5.5,-8.5) AD11(-4.5,-8.5) AD12(-3.5,-8.5) AD13(-2.5,-8.5) AD14(-1.5,-8.5) AD15(-0.5,-8.5) AD16(0.5,-8.5) AD17(1.5,-8.5) AD18(2.5,-8.5) AD19(3.5,-8.5) AD20(4.5,-8.5) AD21(5.5,-8.5) AD22(6.5,-8.5) AD23(7.5,-8.5) AD24(8.5,-8.5) AD25(9.5,-8.5) AD26(10.5,-8.5) AD27(11.5,-8.5) AD28(12.5,-8.5) AD29(13.5,-8.5) AD30(14.5,-8.5) AE1(-14.5,-9.5) AE2(-13.5,-9.5) AE3(-12.5,-9.5) AE4(-11.5,-9.5) AE5(-10.5,-9.5) AE6(-9.5,-9.5) AE7(-8.5,-9.5) AE8(-7.5,-9.5) AE9(-6.5,-9.5) AE10(-5.5,-9.5) AE11(-4.5,-9.5) AE12(-3.5,-9.5) AE13(-2.5,-9.5) AE14(-1.5,-9.5) AE15(-0.5,-9.5) AE16(0.5,-9.5) AE17(1.5,-9.5) AE18(2.5,-9.5) AE19(3.5,-9.5) AE20(4.5,-9.5) AE21(5.5,-9.5) AE22(6.5,-9.5) AE23(7.5,-9.5) AE24(8.5,-9.5) AE25(9.5,-9.5) AE26(10.5,-9.5) AE27(11.5,-9.5) AE28(12.5,-9.5) AE29(13.5,-9.5) AE30(14.5,-9.5) AF1(-14.5,-10.5) AF2(-13.5,-10.5) AF3(-12.5,-10.5) AF4(-11.5,-10.5) AF5(-10.5,-10.5) AF6(-9.5,-10.5) AF7(-8.5,-10.5) AF8(-7.5,-10.5) AF9(-6.5,-10.5) AF10(-5.5,-10.5) AF11(-4.5,-10.5) AF12(-3.5,-10.5) AF13(-2.5,-10.5) AF14(-1.5,-10.5) AF15(-0.5,-10.5) AF16(0.5,-10.5) AF17(1.5,-10.5) AF18(2.5,-10.5) AF19(3.5,-10.5) AF20(4.5,-10.5) AF21(5.5,-10.5) AF22(6.5,-10.5) AF23(7.5,-10.5) AF24(8.5,-10.5) AF25(9.5,-10.5) AF26(10.5,-10.5) AF27(11.5,-10.5) AF28(12.5,-10.5) AF29(13.5,-10.5) AF30(14.5,-10.5) AG1(-14.5,-11.5) AG2(-13.5,-11.5) AG3(-12.5,-11.5) AG4(-11.5,-11.5) AG5(-10.5,-11.5) AG6(-9.5,-11.5) AG7(-8.5,-11.5) AG8(-7.5,-11.5) AG9(-6.5,-11.5) AG10(-5.5,-11.5) AG11(-4.5,-11.5) AG12(-3.5,-11.5) AG13(-2.5,-11.5) AG14(-1.5,-11.5) AG15(-0.5,-11.5) AG16(0.5,-11.5) AG17(1.5,-11.5) AG18(2.5,-11.5) AG19(3.5,-11.5) AG20(4.5,-11.5) AG21(5.5,-11.5) AG22(6.5,-11.5) AG23(7.5,-11.5) AG24(8.5,-11.5) AG25(9.5,-11.5) AG26(10.5,-11.5) AG27(11.5,-11.5) AG28(12.5,-11.5) AG29(13.5,-11.5) AG30(14.5,-11.5) AH1(-14.5,-12.5) AH2(-13.5,-12.5) AH3(-12.5,-12.5) AH4(-11.5,-12.5) AH5(-10.5,-12.5) AH6(-9.5,-12.5) AH7(-8.5,-12.5) AH8(-7.5,-12.5) AH9(-6.5,-12.5) AH10(-5.5,-12.5) AH11(-4.5,-12.5) AH12(-3.5,-12.5) AH13(-2.5,-12.5) AH14(-1.5,-12.5) AH15(-0.5,-12.5) AH16(0.5,-12.5) AH17(1.5,-12.5) AH18(2.5,-12.5) AH19(3.5,-12.5) AH20(4.5,-12.5) AH21(5.5,-12.5) AH22(6.5,-12.5) AH23(7.5,-12.5) AH24(8.5,-12.5) AH25(9.5,-12.5) AH26(10.5,-12.5) AH27(11.5,-12.5) AH28(12.5,-12.5) AH29(13.5,-12.5) AH30(14.5,-12.5) AJ1(-14.5,-13.5) AJ2(-13.5,-13.5) AJ3(-12.5,-13.5) AJ4(-11.5,-13.5) AJ5(-10.5,-13.5) AJ6(-9.5,-13.5) AJ7(-8.5,-13.5) AJ8(-7.5,-13.5) AJ9(-6.5,-13.5) AJ10(-5.5,-13.5) AJ11(-4.5,-13.5) AJ12(-3.5,-13.5) AJ13(-2.5,-13.5) AJ14(-1.5,-13.5) AJ15(-0.5,-13.5) AJ16(0.5,-13.5) AJ17(1.5,-13.5) AJ18(2.5,-13.5) AJ19(3.5,-13.5) AJ20(4.5,-13.5) AJ21(5.5,-13.5) AJ22(6.5,-13.5) AJ23(7.5,-13.5) AJ24(8.5,-13.5) AJ25(9.5,-13.5) AJ26(10.5,-13.5) AJ27(11.5,-13.5) AJ28(12.5,-13.5) AJ29(13.5,-13.5) AJ30(14.5,-13.5) AK2(-13.5,-14.5) AK3(-12.5,-14.5) AK4(-11.5,-14.5) AK5(-10.5,-14.5) AK6(-9.5,-14.5) AK7(-8.5,-14.5) AK8(-7.5,-14.5) AK9(-6.5,-14.5) AK10(-5.5,-14.5) AK11(-4.5,-14.5) AK12(-3.5,-14.5) AK13(-2.5,-14.5) AK14(-1.5,-14.5) AK15(-0.5,-14.5) AK16(0.5,-14.5) AK17(1.5,-14.5) AK18(2.5,-14.5) AK19(3.5,-14.5) AK20(4.5,-14.5) AK21(5.5,-14.5) AK22(6.5,-14.5) AK23(7.5,-14.5) AK24(8.5,-14.5) AK25(9.5,-14.5) AK26(10.5,-14.5) AK27(11.5,-14.5) AK28(12.5,-14.5) AK29(13.5,-14.5) B1(-14.5,13.5) B2(-13.5,13.5) B3(-12.5,13.5) B4(-11.5,13.5) B5(-10.5,13.5) B6(-9.5,13.5) B7(-8.5,13.5) B8(-7.5,13.5) B9(-6.5,13.5) B10(-5.5,13.5) B11(-4.5,13.5) B12(-3.5,13.5) B13(-2.5,13.5) B14(-1.5,13.5) B15(-0.5,13.5) B16(0.5,13.5) B17(1.5,13.5) B18(2.5,13.5) B19(3.5,13.5) B20(4.5,13.5) B21(5.5,13.5) B22(6.5,13.5) B23(7.5,13.5) B24(8.5,13.5) B25(9.5,13.5) B26(10.5,13.5) B27(11.5,13.5) B28(12.5,13.5) B29(13.5,13.5) B30(14.5,13.5) C1(-14.5,12.5) C2(-13.5,12.5) C3(-12.5,12.5) C4(-11.5,12.5) C5(-10.5,12.5) C6(-9.5,12.5) C7(-8.5,12.5) C8(-7.5,12.5) C9(-6.5,12.5) C10(-5.5,12.5) C11(-4.5,12.5) C12(-3.5,12.5) C13(-2.5,12.5) C14(-1.5,12.5) C15(-0.5,12.5) C16(0.5,12.5) C17(1.5,12.5) C18(2.5,12.5) C19(3.5,12.5) C20(4.5,12.5) C21(5.5,12.5) C22(6.5,12.5) C23(7.5,12.5) C24(8.5,12.5) C25(9.5,12.5) C26(10.5,12.5) C27(11.5,12.5) C28(12.5,12.5) C29(13.5,12.5) C30(14.5,12.5) D1(-14.5,11.5) D2(-13.5,11.5) D3(-12.5,11.5) D4(-11.5,11.5) D5(-10.5,11.5) D6(-9.5,11.5) D7(-8.5,11.5) D8(-7.5,11.5) D9(-6.5,11.5) D10(-5.5,11.5) D11(-4.5,11.5) D12(-3.5,11.5) D13(-2.5,11.5) D14(-1.5,11.5) D15(-0.5,11.5) D16(0.5,11.5) D17(1.5,11.5) D18(2.5,11.5) D19(3.5,11.5) D20(4.5,11.5) D21(5.5,11.5) D22(6.5,11.5) D23(7.5,11.5) D24(8.5,11.5) D25(9.5,11.5) D26(10.5,11.5) D27(11.5,11.5) D28(12.5,11.5) D29(13.5,11.5) D30(14.5,11.5) E1(-14.5,10.5) E2(-13.5,10.5) E3(-12.5,10.5) E4(-11.5,10.5) E5(-10.5,10.5) E6(-9.5,10.5) E7(-8.5,10.5) E8(-7.5,10.5) E9(-6.5,10.5) E10(-5.5,10.5) E11(-4.5,10.5) E12(-3.5,10.5) E13(-2.5,10.5) E14(-1.5,10.5) E15(-0.5,10.5) E16(0.5,10.5) E17(1.5,10.5) E18(2.5,10.5) E19(3.5,10.5) E20(4.5,10.5) E21(5.5,10.5) E22(6.5,10.5) E23(7.5,10.5) E24(8.5,10.5) E25(9.5,10.5) E26(10.5,10.5) E27(11.5,10.5) E28(12.5,10.5) E29(13.5,10.5) E30(14.5,10.5) F1(-14.5,9.5) F2(-13.5,9.5) F3(-12.5,9.5) F4(-11.5,9.5) F5(-10.5,9.5) F6(-9.5,9.5) F7(-8.5,9.5) F8(-7.5,9.5) F9(-6.5,9.5) F10(-5.5,9.5) F11(-4.5,9.5) F12(-3.5,9.5) F13(-2.5,9.5) F14(-1.5,9.5) F15(-0.5,9.5) F16(0.5,9.5) F17(1.5,9.5) F18(2.5,9.5) F19(3.5,9.5) F20(4.5,9.5) F21(5.5,9.5) F22(6.5,9.5) F23(7.5,9.5) F24(8.5,9.5) F25(9.5,9.5) F26(10.5,9.5) F27(11.5,9.5) F28(12.5,9.5) F29(13.5,9.5) F30(14.5,9.5) G1(-14.5,8.5) G2(-13.5,8.5) G3(-12.5,8.5) G4(-11.5,8.5) G5(-10.5,8.5) G6(-9.5,8.5) G7(-8.5,8.5) G8(-7.5,8.5) G9(-6.5,8.5) G10(-5.5,8.5) G11(-4.5,8.5) G12(-3.5,8.5) G13(-2.5,8.5) G14(-1.5,8.5) G15(-0.5,8.5) G16(0.5,8.5) G17(1.5,8.5) G18(2.5,8.5) G19(3.5,8.5) G20(4.5,8.5) G21(5.5,8.5) G22(6.5,8.5) G23(7.5,8.5) G24(8.5,8.5) G25(9.5,8.5) G26(10.5,8.5) G27(11.5,8.5) G28(12.5,8.5) G29(13.5,8.5) G30(14.5,8.5) H1(-14.5,7.5) H2(-13.5,7.5) H3(-12.5,7.5) H4(-11.5,7.5) H5(-10.5,7.5) H6(-9.5,7.5) H7(-8.5,7.5) H8(-7.5,7.5) H9(-6.5,7.5) H10(-5.5,7.5) H11(-4.5,7.5) H12(-3.5,7.5) H13(-2.5,7.5) H14(-1.5,7.5) H15(-0.5,7.5) H16(0.5,7.5) H17(1.5,7.5) H18(2.5,7.5) H19(3.5,7.5) H20(4.5,7.5) H21(5.5,7.5) H22(6.5,7.5) H23(7.5,7.5) H24(8.5,7.5) H25(9.5,7.5) H26(10.5,7.5) H27(11.5,7.5) H28(12.5,7.5) H29(13.5,7.5) H30(14.5,7.5) J1(-14.5,6.5) J2(-13.5,6.5) J3(-12.5,6.5) J4(-11.5,6.5) J5(-10.5,6.5) J6(-9.5,6.5) J7(-8.5,6.5) J8(-7.5,6.5) J9(-6.5,6.5) J10(-5.5,6.5) J11(-4.5,6.5) J12(-3.5,6.5) J13(-2.5,6.5) J14(-1.5,6.5) J15(-0.5,6.5) J16(0.5,6.5) J17(1.5,6.5) J18(2.5,6.5) J19(3.5,6.5) J20(4.5,6.5) J21(5.5,6.5) J22(6.5,6.5) J23(7.5,6.5) J24(8.5,6.5) J25(9.5,6.5) J26(10.5,6.5) J27(11.5,6.5) J28(12.5,6.5) J29(13.5,6.5) J30(14.5,6.5) K1(-14.5,5.5) K2(-13.5,5.5) K3(-12.5,5.5) K4(-11.5,5.5) K5(-10.5,5.5) K6(-9.5,5.5) K7(-8.5,5.5) K8(-7.5,5.5) K9(-6.5,5.5) K10(-5.5,5.5) K11(-4.5,5.5) K12(-3.5,5.5) K13(-2.5,5.5) K14(-1.5,5.5) K15(-0.5,5.5) K16(0.5,5.5) K17(1.5,5.5) K18(2.5,5.5) K19(3.5,5.5) K20(4.5,5.5) K21(5.5,5.5) K22(6.5,5.5) K23(7.5,5.5) K24(8.5,5.5) K25(9.5,5.5) K26(10.5,5.5) K27(11.5,5.5) K28(12.5,5.5) K29(13.5,5.5) K30(14.5,5.5) L1(-14.5,4.5) L2(-13.5,4.5) L3(-12.5,4.5) L4(-11.5,4.5) L5(-10.5,4.5) L6(-9.5,4.5) L7(-8.5,4.5) L8(-7.5,4.5) L9(-6.5,4.5) L10(-5.5,4.5) L11(-4.5,4.5) L12(-3.5,4.5) L13(-2.5,4.5) L14(-1.5,4.5) L15(-0.5,4.5) L16(0.5,4.5) L17(1.5,4.5) L18(2.5,4.5) L19(3.5,4.5) L20(4.5,4.5) L21(5.5,4.5) L22(6.5,4.5) L23(7.5,4.5) L24(8.5,4.5) L25(9.5,4.5) L26(10.5,4.5) L27(11.5,4.5) L28(12.5,4.5) L29(13.5,4.5) L30(14.5,4.5) M1(-14.5,3.5) M2(-13.5,3.5) M3(-12.5,3.5) M4(-11.5,3.5) M5(-10.5,3.5) M6(-9.5,3.5) M7(-8.5,3.5) M8(-7.5,3.5) M9(-6.5,3.5) M10(-5.5,3.5) M11(-4.5,3.5) M12(-3.5,3.5) M13(-2.5,3.5) M14(-1.5,3.5) M15(-0.5,3.5) M16(0.5,3.5) M17(1.5,3.5) M18(2.5,3.5) M19(3.5,3.5) M20(4.5,3.5) M21(5.5,3.5) M22(6.5,3.5) M23(7.5,3.5) M24(8.5,3.5) M25(9.5,3.5) M26(10.5,3.5) M27(11.5,3.5) M28(12.5,3.5) M29(13.5,3.5) M30(14.5,3.5) N1(-14.5,2.5) N2(-13.5,2.5) N3(-12.5,2.5) N4(-11.5,2.5) N5(-10.5,2.5) N6(-9.5,2.5) N7(-8.5,2.5) N8(-7.5,2.5) N9(-6.5,2.5) N10(-5.5,2.5) N11(-4.5,2.5) N12(-3.5,2.5) N13(-2.5,2.5) N14(-1.5,2.5) N15(-0.5,2.5) N16(0.5,2.5) N17(1.5,2.5) N18(2.5,2.5) N19(3.5,2.5) N20(4.5,2.5) N21(5.5,2.5) N22(6.5,2.5) N23(7.5,2.5) N24(8.5,2.5) N25(9.5,2.5) N26(10.5,2.5) N27(11.5,2.5) N28(12.5,2.5) N29(13.5,2.5) N30(14.5,2.5) P1(-14.5,1.5) P2(-13.5,1.5) P3(-12.5,1.5) P4(-11.5,1.5) P5(-10.5,1.5) P6(-9.5,1.5) P7(-8.5,1.5) P8(-7.5,1.5) P9(-6.5,1.5) P10(-5.5,1.5) P11(-4.5,1.5) P12(-3.5,1.5) P13(-2.5,1.5) P14(-1.5,1.5) P15(-0.5,1.5) P16(0.5,1.5) P17(1.5,1.5) P18(2.5,1.5) P19(3.5,1.5) P20(4.5,1.5) P21(5.5,1.5) P22(6.5,1.5) P23(7.5,1.5) P24(8.5,1.5) P25(9.5,1.5) P26(10.5,1.5) P27(11.5,1.5) P28(12.5,1.5) P29(13.5,1.5) P30(14.5,1.5) R1(-14.5,0.5) R2(-13.5,0.5) R3(-12.5,0.5) R4(-11.5,0.5) R5(-10.5,0.5) R6(-9.5,0.5) R7(-8.5,0.5) R8(-7.5,0.5) R9(-6.5,0.5) R10(-5.5,0.5) R11(-4.5,0.5) R12(-3.5,0.5) R13(-2.5,0.5) R14(-1.5,0.5) R15(-0.5,0.5) R16(0.5,0.5) R17(1.5,0.5) R18(2.5,0.5) R19(3.5,0.5) R20(4.5,0.5) R21(5.5,0.5) R22(6.5,0.5) R23(7.5,0.5) R24(8.5,0.5) R25(9.5,0.5) R26(10.5,0.5) R27(11.5,0.5) R28(12.5,0.5) R29(13.5,0.5) R30(14.5,0.5) T1(-14.5,-0.5) T2(-13.5,-0.5) T3(-12.5,-0.5) T4(-11.5,-0.5) T5(-10.5,-0.5) T6(-9.5,-0.5) T7(-8.5,-0.5) T8(-7.5,-0.5) T9(-6.5,-0.5) T10(-5.5,-0.5) T11(-4.5,-0.5) T12(-3.5,-0.5) T13(-2.5,-0.5) T14(-1.5,-0.5) T15(-0.5,-0.5) T16(0.5,-0.5) T17(1.5,-0.5) T18(2.5,-0.5) T19(3.5,-0.5) T20(4.5,-0.5) T21(5.5,-0.5) T22(6.5,-0.5) T23(7.5,-0.5) T24(8.5,-0.5) T25(9.5,-0.5) T26(10.5,-0.5) T27(11.5,-0.5) T28(12.5,-0.5) T29(13.5,-0.5) T30(14.5,-0.5) U1(-14.5,-1.5) U2(-13.5,-1.5) U3(-12.5,-1.5) U4(-11.5,-1.5) U5(-10.5,-1.5) U6(-9.5,-1.5) U7(-8.5,-1.5) U8(-7.5,-1.5) U9(-6.5,-1.5) U10(-5.5,-1.5) U11(-4.5,-1.5) U12(-3.5,-1.5) U13(-2.5,-1.5) U14(-1.5,-1.5) U15(-0.5,-1.5) U16(0.5,-1.5) U17(1.5,-1.5) U18(2.5,-1.5) U19(3.5,-1.5) U20(4.5,-1.5) U21(5.5,-1.5) U22(6.5,-1.5) U23(7.5,-1.5) U24(8.5,-1.5) U25(9.5,-1.5) U26(10.5,-1.5) U27(11.5,-1.5) U28(12.5,-1.5) U29(13.5,-1.5) U30(14.5,-1.5) V1(-14.5,-2.5) V2(-13.5,-2.5) V3(-12.5,-2.5) V4(-11.5,-2.5) V5(-10.5,-2.5) V6(-9.5,-2.5) V7(-8.5,-2.5) V8(-7.5,-2.5) V9(-6.5,-2.5) V10(-5.5,-2.5) V11(-4.5,-2.5) V12(-3.5,-2.5) V13(-2.5,-2.5) V14(-1.5,-2.5) V15(-0.5,-2.5) V16(0.5,-2.5) V17(1.5,-2.5) V18(2.5,-2.5) V19(3.5,-2.5) V20(4.5,-2.5) V21(5.5,-2.5) V22(6.5,-2.5) V23(7.5,-2.5) V24(8.5,-2.5) V25(9.5,-2.5) V26(10.5,-2.5) V27(11.5,-2.5) V28(12.5,-2.5) V29(13.5,-2.5) V30(14.5,-2.5) W1(-14.5,-3.5) W2(-13.5,-3.5) W3(-12.5,-3.5) W4(-11.5,-3.5) W5(-10.5,-3.5) W6(-9.5,-3.5) W7(-8.5,-3.5) W8(-7.5,-3.5) W9(-6.5,-3.5) W10(-5.5,-3.5) W11(-4.5,-3.5) W12(-3.5,-3.5) W13(-2.5,-3.5) W14(-1.5,-3.5) W15(-0.5,-3.5) W16(0.5,-3.5) W17(1.5,-3.5) W18(2.5,-3.5) W19(3.5,-3.5) W20(4.5,-3.5) W21(5.5,-3.5) W22(6.5,-3.5) W23(7.5,-3.5) W24(8.5,-3.5) W25(9.5,-3.5) W26(10.5,-3.5) W27(11.5,-3.5) W28(12.5,-3.5) W29(13.5,-3.5) W30(14.5,-3.5) Y1(-14.5,-4.5) Y2(-13.5,-4.5) Y3(-12.5,-4.5) Y4(-11.5,-4.5) Y5(-10.5,-4.5) Y6(-9.5,-4.5) Y7(-8.5,-4.5) Y8(-7.5,-4.5) Y9(-6.5,-4.5) Y10(-5.5,-4.5) Y11(-4.5,-4.5) Y12(-3.5,-4.5) Y13(-2.5,-4.5) Y14(-1.5,-4.5) Y15(-0.5,-4.5) Y16(0.5,-4.5) Y17(1.5,-4.5) Y18(2.5,-4.5) Y19(3.5,-4.5) Y20(4.5,-4.5) Y21(5.5,-4.5) Y22(6.5,-4.5) Y23(7.5,-4.5) Y24(8.5,-4.5) Y25(9.5,-4.5) Y26(10.5,-4.5) Y27(11.5,-4.5) Y28(12.5,-4.5) Y29(13.5,-4.5) Y30(14.5,-4.5)
Top Overlay:
  circle w0.25: c-16.15,14.5 r0.125
  region: -14.5,15.5 -15.5,14.5 -15.5,15.5
  lines w0.2: -15.5,14.5 -14.5,15.5 ; -15.5,-15.5 -15.5,15.5 15.5,15.5 15.5,-15.5 -15.5,-15.5
Mechanical 13:
  lines w0.1: -15.5,-15.5 -15.5,15.5 15.5,15.5 15.5,-15.5 -15.5,-15.5
Mechanical 15:
  lines w0.1: -0.5,0 0.5,0 ; 0,-0.5 0,0.5 ; -16.5,-16.5 -16.5,16.5 16.5,16.5 16.5,-16.5 -16.5,-16.5
3D body: height 3.4, standoff 0, extent -15.5,-15.5 15.5,15.5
